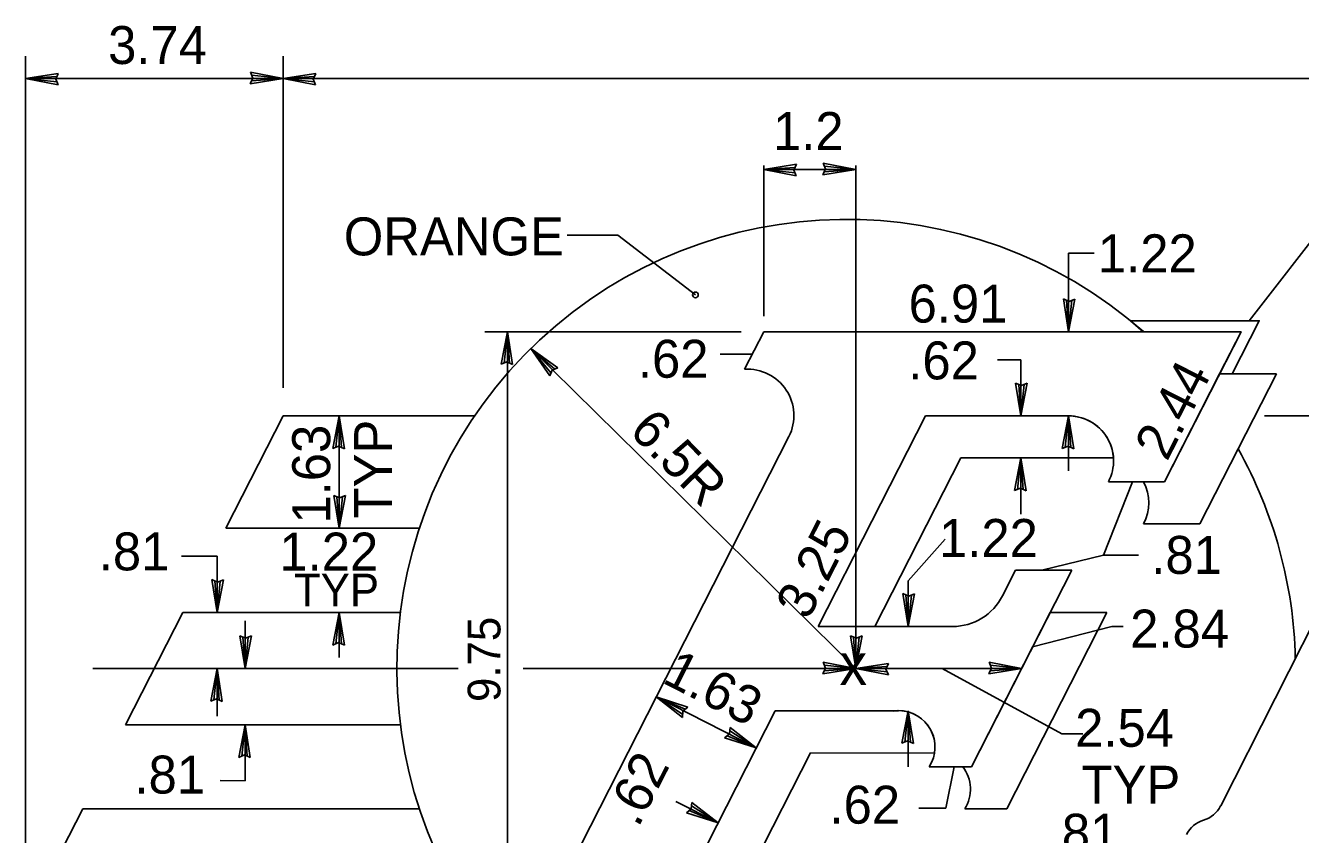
# Model space of a CAD drawing. Extents: x 10268197 to 10269179, y 2141503 to 2142677.
# Drawn here: x 10268592.24 to 10268612.19, y 2142153.36 to 2142166.03 of the extents above; entities that cross this region are included whole.
import ezdxf

# ---------------------------------------------------------------- set-up
doc = ezdxf.new("R2010")
doc.units = 0
for name, color, linetype in [('1', 7, 'Continuous'), ('21', 7, 'Continuous'), ('Default', 7, 'Continuous')]:
    doc.layers.add(name, color=color, linetype=linetype)

msp = doc.modelspace()

# ---------------------------------------------------------------- linework, layer by layer
at = {"layer": '1'}
for p, q in [((10268592.239, 2142152.526), (10268592.239, 2142165.546)), ((10268596.269, 2142160.355), (10268596.269, 2142165.546)), ((10268596.269, 2142165.194), (10268596.782, 2142165.276)), ((10268596.742, 2142165.186), (10268596.782, 2142165.276)), ((10268596.269, 2142165.194), (10268592.239, 2142165.194)), ((10268596.269, 2142165.194), (10268596.761, 2142165.229)), ((10268596.269, 2142165.194), (10268617.622, 2142165.194)), ((10268596.269, 2142165.194), (10268596.779, 2142165.095)), ((10268596.269, 2142165.194), (10268596.76, 2142165.143)), ((10268596.779, 2142165.095), (10268596.742, 2142165.186)), ((10268603.79, 2142163.772), (10268604.305, 2142163.853)), ((10268604.264, 2142163.764), (10268604.305, 2142163.853)), ((10268603.79, 2142161.475), (10268603.79, 2142163.833)), ((10268603.79, 2142163.772), (10268604.283, 2142163.806)), ((10268603.79, 2142163.772), (10268605.232, 2142163.772)), ((10268603.79, 2142163.772), (10268604.301, 2142163.673)), ((10268603.79, 2142163.772), (10268604.282, 2142163.721)), ((10268604.301, 2142163.673), (10268604.264, 2142163.764)), ((10268605.232, 2142155.962), (10268605.232, 2142163.833)), ((10268611.389, 2142161.404), (10268613.109, 2142163.626)), ((10268600.715, 2142162.745), (10268601.51, 2142162.745)), ((10268601.51, 2142162.745), (10268602.722, 2142161.81)), ((10268608.561, 2142162.465), (10268608.561, 2142161.234)), ((10268608.561, 2142162.465), (10268608.959, 2142162.465)), ((10268608.561, 2142161.234), (10268608.48, 2142161.748)), ((10268608.57, 2142161.707), (10268608.48, 2142161.748)), ((10268608.561, 2142161.234), (10268608.527, 2142161.726)), ((10268608.561, 2142161.234), (10268608.661, 2142161.744)), ((10268608.561, 2142161.234), (10268608.613, 2142161.725)), ((10268608.661, 2142161.744), (10268608.57, 2142161.707)), ((10268603.439, 2142161.234), (10268599.428, 2142161.234)), ((10268599.779, 2142161.234), (10268599.68, 2142160.723)), ((10268599.779, 2142161.234), (10268599.728, 2142160.743)), ((10268599.779, 2142150.689), (10268599.779, 2142161.234)), ((10268599.779, 2142161.234), (10268599.86, 2142160.72)), ((10268599.779, 2142161.234), (10268599.813, 2142160.742)), ((10268605.232, 2142155.962), (10268600.148, 2142160.97)), ((10268600.148, 2142160.97), (10268600.571, 2142160.667)), ((10268600.148, 2142160.97), (10268600.443, 2142160.541)), ((10268600.148, 2142160.97), (10268600.462, 2142160.588)), ((10268600.148, 2142160.97), (10268600.523, 2142160.649)), ((10268603.611, 2142160.882), (10268603.111, 2142160.882)), ((10268599.68, 2142160.723), (10268599.771, 2142160.761)), ((10268599.771, 2142160.761), (10268599.86, 2142160.72)), ((10268600.48, 2142160.632), (10268600.571, 2142160.667)), ((10268607.815, 2142160.794), (10268607.45, 2142160.794)), ((10268607.815, 2142160.794), (10268607.815, 2142159.916)), ((10268600.443, 2142160.541), (10268600.48, 2142160.632)), ((10268610.061, 2142158.883), (10268610.924, 2142160.575)), ((10268611.812, 2142160.575), (10268610.614, 2142158.226)), ((10268610.924, 2142160.575), (10268611.812, 2142160.575)), ((10268607.815, 2142159.916), (10268607.733, 2142160.429)), ((10268607.823, 2142160.389), (10268607.733, 2142160.429)), ((10268607.815, 2142159.916), (10268607.781, 2142160.408)), ((10268607.815, 2142159.916), (10268607.914, 2142160.426)), ((10268607.815, 2142159.916), (10268607.866, 2142160.406)), ((10268607.914, 2142160.426), (10268607.823, 2142160.389)), ((10268597.147, 2142159.916), (10268597.048, 2142159.405)), ((10268597.147, 2142159.916), (10268597.096, 2142159.424)), ((10268597.147, 2142158.158), (10268597.147, 2142159.916)), ((10268597.147, 2142159.916), (10268597.229, 2142159.402)), ((10268597.147, 2142159.916), (10268597.182, 2142159.424)), ((10268604.643, 2142156.621), (10268606.322, 2142159.916)), ((10268606.322, 2142159.916), (10268608.561, 2142159.916)), ((10268608.561, 2142159.916), (10268608.462, 2142159.405)), ((10268608.561, 2142159.916), (10268608.51, 2142159.424)), ((10268608.561, 2142159.916), (10268608.643, 2142159.402)), ((10268608.561, 2142159.916), (10268608.596, 2142159.424)), ((10268608.561, 2142159.916), (10268608.561, 2142159.057)), ((10268597.048, 2142159.405), (10268597.139, 2142159.442)), ((10268597.139, 2142159.442), (10268597.229, 2142159.402)), ((10268606.874, 2142159.257), (10268605.531, 2142156.621)), ((10268609.263, 2142159.257), (10268606.874, 2142159.257)), ((10268607.815, 2142159.257), (10268607.716, 2142158.746)), ((10268607.815, 2142159.257), (10268607.764, 2142158.766)), ((10268607.815, 2142159.257), (10268607.815, 2142158.378)), ((10268607.815, 2142159.257), (10268607.897, 2142158.743)), ((10268607.815, 2142159.257), (10268607.85, 2142158.765)), ((10268608.462, 2142159.405), (10268608.553, 2142159.442)), ((10268608.553, 2142159.442), (10268608.643, 2142159.402)), ((10268609.109, 2142157.735), (10268609.56, 2142158.885)), ((10268609.735, 2142158.883), (10268610.061, 2142158.883)), ((10268597.147, 2142158.158), (10268597.066, 2142158.672)), ((10268597.155, 2142158.631), (10268597.066, 2142158.672)), ((10268597.147, 2142158.158), (10268597.247, 2142158.669)), ((10268597.247, 2142158.669), (10268597.155, 2142158.631)), ((10268607.716, 2142158.746), (10268607.807, 2142158.783)), ((10268607.807, 2142158.783), (10268607.897, 2142158.743)), ((10268597.147, 2142158.158), (10268597.112, 2142158.65)), ((10268597.147, 2142158.158), (10268597.199, 2142158.649)), ((10268610.614, 2142158.226), (10268609.735, 2142158.226)), ((10268606.63, 2142157.989), (10268606.051, 2142157.335)), ((10268595.236, 2142157.719), (10268594.679, 2142157.723)), ((10268595.236, 2142156.84), (10268595.236, 2142157.719)), ((10268609.109, 2142157.735), (10268608.142, 2142157.499)), ((10268609.655, 2142157.735), (10268609.109, 2142157.735)), ((10268595.236, 2142156.84), (10268595.154, 2142157.354)), ((10268595.244, 2142157.313), (10268595.154, 2142157.354)), ((10268595.236, 2142156.84), (10268595.201, 2142157.333)), ((10268595.236, 2142156.84), (10268595.335, 2142157.351)), ((10268595.236, 2142156.84), (10268595.287, 2142157.331)), ((10268595.335, 2142157.351), (10268595.244, 2142157.313)), ((10268606.051, 2142157.335), (10268606.051, 2142156.621)), ((10268606.051, 2142156.621), (10268605.969, 2142157.134)), ((10268606.059, 2142157.093), (10268605.969, 2142157.134)), ((10268606.051, 2142156.621), (10268606.016, 2142157.113)), ((10268606.051, 2142156.621), (10268606.15, 2142157.132)), ((10268606.051, 2142156.621), (10268606.102, 2142157.111)), ((10268606.15, 2142157.132), (10268606.059, 2142157.093)), ((10268595.675, 2142155.962), (10268595.675, 2142156.708)), ((10268597.147, 2142156.84), (10268597.048, 2142156.33)), ((10268597.147, 2142156.84), (10268597.096, 2142156.349)), ((10268597.147, 2142156.137), (10268597.147, 2142156.84)), ((10268597.147, 2142156.84), (10268597.229, 2142156.326)), ((10268597.147, 2142156.84), (10268597.182, 2142156.348)), ((10268607.043, 2142154.424), (10268608.274, 2142156.84)), ((10268609.161, 2142156.84), (10268607.595, 2142153.765)), ((10268608.274, 2142156.84), (10268609.161, 2142156.84)), ((10268595.675, 2142155.962), (10268595.594, 2142156.475)), ((10268595.683, 2142156.435), (10268595.594, 2142156.475)), ((10268595.675, 2142155.962), (10268595.774, 2142156.472)), ((10268595.774, 2142156.472), (10268595.683, 2142156.435)), ((10268605.531, 2142156.621), (10268604.643, 2142156.621)), ((10268605.232, 2142155.962), (10268605.15, 2142156.475)), ((10268605.24, 2142156.435), (10268605.15, 2142156.475)), ((10268605.232, 2142155.962), (10268605.33, 2142156.472)), ((10268605.33, 2142156.472), (10268605.24, 2142156.435)), ((10268609.24, 2142156.621), (10268607.999, 2142156.299)), ((10268609.415, 2142156.621), (10268609.24, 2142156.621)), ((10268595.675, 2142155.962), (10268595.641, 2142156.453)), ((10268595.675, 2142155.962), (10268595.726, 2142156.452)), ((10268597.048, 2142156.33), (10268597.139, 2142156.367)), ((10268597.139, 2142156.367), (10268597.229, 2142156.326)), ((10268605.232, 2142155.962), (10268605.197, 2142156.453)), ((10268605.232, 2142155.962), (10268605.283, 2142156.452)), ((10268605.232, 2142155.962), (10268604.721, 2142156.061)), ((10268604.721, 2142156.061), (10268604.758, 2142155.97)), ((10268607.827, 2142155.962), (10268607.316, 2142156.061)), ((10268607.316, 2142156.061), (10268607.353, 2142155.97)), ((10268599.012, 2142155.962), (10268593.295, 2142155.962)), ((10268595.236, 2142155.962), (10268595.137, 2142155.451)), ((10268595.236, 2142155.962), (10268595.184, 2142155.471)), ((10268595.236, 2142155.215), (10268595.236, 2142155.962)), ((10268595.236, 2142155.962), (10268595.317, 2142155.448)), ((10268595.236, 2142155.962), (10268595.27, 2142155.469)), ((10268605.232, 2142155.962), (10268600.025, 2142155.962)), ((10268604.758, 2142155.97), (10268604.717, 2142155.88)), ((10268605.232, 2142155.962), (10268604.717, 2142155.88)), ((10268605.232, 2142155.962), (10268604.74, 2142155.927)), ((10268605.232, 2142155.962), (10268604.741, 2142156.013)), ((10268605.232, 2142155.962), (10268605.745, 2142156.043)), ((10268605.232, 2142155.962), (10268605.724, 2142155.996)), ((10268607.827, 2142155.962), (10268605.232, 2142155.962)), ((10268605.232, 2142155.962), (10268605.742, 2142155.863)), ((10268605.232, 2142155.962), (10268605.722, 2142155.91)), ((10268605.704, 2142155.954), (10268605.745, 2142156.043)), ((10268605.742, 2142155.863), (10268605.704, 2142155.954)), ((10268608.454, 2142154.939), (10268606.584, 2142155.962)), ((10268607.353, 2142155.97), (10268607.313, 2142155.88)), ((10268607.827, 2142155.962), (10268607.313, 2142155.88)), ((10268607.827, 2142155.962), (10268607.334, 2142155.927)), ((10268607.827, 2142155.962), (10268607.335, 2142156.013)), ((10268595.137, 2142155.451), (10268595.228, 2142155.489)), ((10268595.228, 2142155.489), (10268595.317, 2142155.448)), ((10268603.675, 2142154.719), (10268602.108, 2142155.517)), ((10268602.108, 2142155.517), (10268602.603, 2142155.356)), ((10268602.108, 2142155.517), (10268602.518, 2142155.197)), ((10268602.108, 2142155.517), (10268602.522, 2142155.249)), ((10268602.108, 2142155.517), (10268602.562, 2142155.324)), ((10268602.517, 2142152.447), (10268603.972, 2142155.302)), ((10268602.518, 2142155.197), (10268602.526, 2142155.295)), ((10268602.526, 2142155.295), (10268602.603, 2142155.356)), ((10268603.972, 2142155.302), (10268605.817, 2142155.296)), ((10268606.051, 2142155.302), (10268605.952, 2142154.792)), ((10268606.051, 2142155.302), (10268605.999, 2142154.812)), ((10268606.051, 2142155.302), (10268606.132, 2142154.789)), ((10268606.051, 2142155.302), (10268606.085, 2142154.81)), ((10268606.051, 2142155.302), (10268606.051, 2142154.424)), ((10268595.675, 2142155.083), (10268595.576, 2142154.572)), ((10268595.675, 2142155.083), (10268595.624, 2142154.592)), ((10268595.675, 2142154.204), (10268595.675, 2142155.083)), ((10268595.675, 2142155.083), (10268595.757, 2142154.569)), ((10268595.675, 2142155.083), (10268595.709, 2142154.591)), ((10268603.257, 2142154.941), (10268603.179, 2142154.879)), ((10268603.675, 2142154.719), (10268603.179, 2142154.879)), ((10268603.675, 2142154.719), (10268603.22, 2142154.911)), ((10268603.264, 2142155.039), (10268603.257, 2142154.941)), ((10268603.675, 2142154.719), (10268603.26, 2142154.988)), ((10268603.675, 2142154.719), (10268603.264, 2142155.039)), ((10268608.782, 2142154.939), (10268608.454, 2142154.939)), ((10268605.952, 2142154.792), (10268606.043, 2142154.83)), ((10268606.043, 2142154.83), (10268606.132, 2142154.789)), ((10268595.576, 2142154.572), (10268595.667, 2142154.61)), ((10268595.667, 2142154.61), (10268595.757, 2142154.569)), ((10268604.523, 2142154.642), (10268603.404, 2142152.447)), ((10268606.463, 2142154.636), (10268604.523, 2142154.642)), ((10268606.638, 2142153.776), (10268606.77, 2142154.424)), ((10268606.905, 2142154.424), (10268607.043, 2142154.424)), ((10268595.675, 2142154.204), (10268595.286, 2142154.208)), ((10268603.076, 2142153.545), (10268602.413, 2142153.883)), ((10268602.666, 2142153.865), (10268602.658, 2142153.767)), ((10268603.076, 2142153.545), (10268602.666, 2142153.865)), ((10268602.658, 2142153.767), (10268602.581, 2142153.705)), ((10268603.076, 2142153.545), (10268602.581, 2142153.705)), ((10268603.076, 2142153.545), (10268602.622, 2142153.738)), ((10268603.076, 2142153.545), (10268602.662, 2142153.814)), ((10268606.217, 2142153.776), (10268606.638, 2142153.776)), ((10268607.595, 2142153.765), (10268606.936, 2142153.765))]:
    msp.add_line(p, q, dxfattribs=at)
msp.add_lwpolyline([(10268609.53, 2142161.404), (10268611.544, 2142161.404), (10268611.122, 2142160.575), (10268610.924, 2142160.575), (10268611.26, 2142161.234), (10268609.73, 2142161.234)], close=True, dxfattribs=at)
msp.add_circle((10268602.722, 2142161.81), 0.0439, dxfattribs=at)
for centre, radius, start, end in [((10268608.562, 2142159.213), 0.703, 3.5833, 90), ((10268609.113, 2142158.554), 0.703, 332.2089, 27.9127), ((10268605.9, 2142154.732), 0.571, 350.3502, 98.3344), ((10268606.455, 2142154.073), 0.571, 327.421, 37.9799)]:
    msp.add_arc(centre, radius, start, end, dxfattribs=at)
at = {"layer": '21'}
for p, q in [((10268592.239, 2142165.194), (10268592.753, 2142165.276)), ((10268592.712, 2142165.186), (10268592.753, 2142165.276)), ((10268596.269, 2142165.194), (10268595.758, 2142165.293)), ((10268595.758, 2142165.293), (10268595.795, 2142165.203)), ((10268596.269, 2142165.194), (10268595.778, 2142165.246)), ((10268592.239, 2142165.194), (10268592.732, 2142165.229)), ((10268592.239, 2142165.194), (10268592.75, 2142165.095)), ((10268592.239, 2142165.194), (10268592.73, 2142165.143)), ((10268592.75, 2142165.095), (10268592.712, 2142165.186)), ((10268595.795, 2142165.203), (10268595.755, 2142165.112)), ((10268596.269, 2142165.194), (10268595.755, 2142165.112)), ((10268596.269, 2142165.194), (10268595.777, 2142165.16)), ((10268605.232, 2142163.772), (10268604.721, 2142163.871)), ((10268604.721, 2142163.871), (10268604.758, 2142163.78)), ((10268604.758, 2142163.78), (10268604.717, 2142163.69)), ((10268605.232, 2142163.772), (10268604.717, 2142163.69)), ((10268605.232, 2142163.772), (10268604.74, 2142163.737)), ((10268605.232, 2142163.772), (10268604.741, 2142163.823))]:
    msp.add_line(p, q, dxfattribs=at)
at = {"layer": 'Default'}
for p, q in [((10268609.53, 2142161.404), (10268611.544, 2142161.404)), ((10268611.544, 2142161.404), (10268611.122, 2142160.575)), ((10268603.491, 2142160.645), (10268603.79, 2142161.234)), ((10268603.79, 2142161.234), (10268611.26, 2142161.234)), ((10268611.26, 2142161.234), (10268610.063, 2142158.885)), ((10268610.061, 2142158.883), (10268610.924, 2142160.575)), ((10268611.812, 2142160.575), (10268610.614, 2142158.226)), ((10268610.924, 2142160.575), (10268611.812, 2142160.575)), ((10268596.269, 2142159.916), (10268595.373, 2142158.158)), ((10268596.269, 2142159.916), (10268599.268, 2142159.916)), ((10268606.322, 2142159.916), (10268604.643, 2142156.621)), ((10268604.643, 2142156.621), (10268606.322, 2142159.916)), ((10268608.561, 2142159.916), (10268606.322, 2142159.916)), ((10268606.322, 2142159.916), (10268608.561, 2142159.916)), ((10268611.626, 2142159.916), (10268636.689, 2142159.916)), ((10268600.538, 2142152.436), (10268604.184, 2142159.592)), ((10268606.874, 2142159.257), (10268605.531, 2142156.621)), ((10268609.263, 2142159.257), (10268606.874, 2142159.257)), ((10268610.063, 2142158.885), (10268609.184, 2142158.885)), ((10268609.735, 2142158.883), (10268610.061, 2142158.883)), ((10268595.373, 2142158.158), (10268598.403, 2142158.158)), ((10268610.614, 2142158.226), (10268609.735, 2142158.226)), ((10268613.116, 2142158.113), (10268610.941, 2142153.811)), ((10268608.61, 2142157.499), (10268607.043, 2142154.424)), ((10268607.527, 2142157.1), (10268607.731, 2142157.499)), ((10268607.731, 2142157.499), (10268608.61, 2142157.499)), ((10268594.702, 2142156.84), (10268593.806, 2142155.083)), ((10268594.702, 2142156.84), (10268598.106, 2142156.84)), ((10268607.043, 2142154.424), (10268608.274, 2142156.84)), ((10268609.161, 2142156.84), (10268607.595, 2142153.765)), ((10268608.274, 2142156.84), (10268609.161, 2142156.84)), ((10268604.643, 2142156.621), (10268606.745, 2142156.621)), ((10268605.531, 2142156.621), (10268604.643, 2142156.621)), ((10268603.972, 2142155.302), (10268602.517, 2142152.447)), ((10268602.517, 2142152.447), (10268603.972, 2142155.302)), ((10268605.9, 2142155.302), (10268603.972, 2142155.302)), ((10268603.972, 2142155.302), (10268605.817, 2142155.296)), ((10268593.806, 2142155.083), (10268598.106, 2142155.083)), ((10268604.523, 2142154.642), (10268603.404, 2142152.447)), ((10268606.463, 2142154.636), (10268604.523, 2142154.642)), ((10268607.043, 2142154.424), (10268606.381, 2142154.424)), ((10268606.905, 2142154.424), (10268607.043, 2142154.424)), ((10268593.135, 2142153.765), (10268592.239, 2142152.007)), ((10268593.135, 2142153.765), (10268598.403, 2142153.765)), ((10268607.595, 2142153.765), (10268606.936, 2142153.765))]:
    msp.add_line(p, q, dxfattribs=at)
for centre, radius, start, end in [((10268605.081, 2142155.962), 7.03, 48.5904, 217.4725), ((10268603.539, 2142159.922), 0.725, 332.9998, 93.8045), ((10268608.562, 2142159.213), 0.703, 332.2089, 90), ((10268608.562, 2142159.213), 0.703, 3.5833, 90), ((10268605.081, 2142155.962), 7.03, 1.2967, 29.2778), ((10268609.113, 2142158.554), 0.703, 332.2089, 27.9127), ((10268606.745, 2142157.499), 0.879, 270, 332.9883), ((10268605.9, 2142154.732), 0.571, 350.3502, 98.3344), ((10268605.9, 2142154.732), 0.571, 327.421, 90), ((10268606.455, 2142154.073), 0.571, 327.421, 37.9799)]:
    msp.add_arc(centre, radius, start, end, dxfattribs=at)
for centre, start_param, end_param in [((10268610.549, 2142154.012), 0.286787, 1.099486), ((10268610.798, 2142153.163), 3.428379, 4.240701)]:
    msp.add_ellipse(centre, major_axis=(0, -0.443), ratio=0.992614, start_param=start_param, end_param=end_param, dxfattribs=at)

# ---------------------------------------------------------------- texts
at = {"layer": '1'}
for s, height, p in [('3.74', 0.5942, (10268593.532, 2142165.423)), ('1.2', 0.5942, (10268603.936, 2142164.077)), ('ORANGE', 0.5942, (10268597.22, 2142162.428)), ('1.22', 0.5942, (10268609.02, 2142162.163)), ('6.91', 0.5942, (10268606.058, 2142161.376)), ('.62', 0.5942, (10268601.822, 2142160.513)), ('.62', 0.5942, (10268606.053, 2142160.487)), ('1.22', 0.5942, (10268606.534, 2142157.708)), ('.81', 0.5942, (10268593.386, 2142157.498)), ('1.22', 0.5942, (10268596.212, 2142157.495)), ('.81', 0.5942, (10268609.856, 2142157.443)), ('TYP', 0.5125, (10268596.439, 2142156.934)), ('2.84', 0.5942, (10268609.525, 2142156.29)), ('x', 0.641, (10268604.978, 2142155.706)), ('2.54', 0.5942, (10268608.664, 2142154.737)), ('.81', 0.5942, (10268593.944, 2142154.005)), ('TYP', 0.5942, (10268608.764, 2142153.846)), ('.62', 0.5942, (10268604.82, 2142153.534)), ('.81', 0.5942, (10268608.235, 2142153.095))]:
    msp.add_text(s, height=height, dxfattribs=at).set_placement(p)
for s, height, rotation, p in [('2.44', 0.5942, 63, (10268610.101, 2142159.19)), ('6.5R', 0.5942, 314.1812, (10268601.667, 2142159.664)), ('1.63', 0.5942, 90, (10268597.007, 2142158.231)), ('TYP', 0.5942, 90, (10268597.975, 2142158.311)), ('3.25', 0.5942, 63.0402, (10268604.486, 2142156.702)), ('9.75', 0.5125, 90, (10268599.671, 2142155.438)), ('1.63', 0.5942, 332.9866, (10268602.182, 2142155.751)), ('.62', 0.5942, 63.0402, (10268601.827, 2142153.46))]:
    msp.add_text(s, height=height, rotation=rotation, dxfattribs=at).set_placement(p)

doc.saveas('drawing.dxf')
